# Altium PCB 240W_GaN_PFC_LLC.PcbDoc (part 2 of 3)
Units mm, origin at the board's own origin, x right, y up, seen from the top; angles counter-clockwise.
Board outline 105 x 71.8 mm, 4 copper layers (Top Layer, Layer 1, Layer 2, Bottom Layer), stack 1.787 mm thick; 165 components, 88 nets, 549 pads, 326 vias.
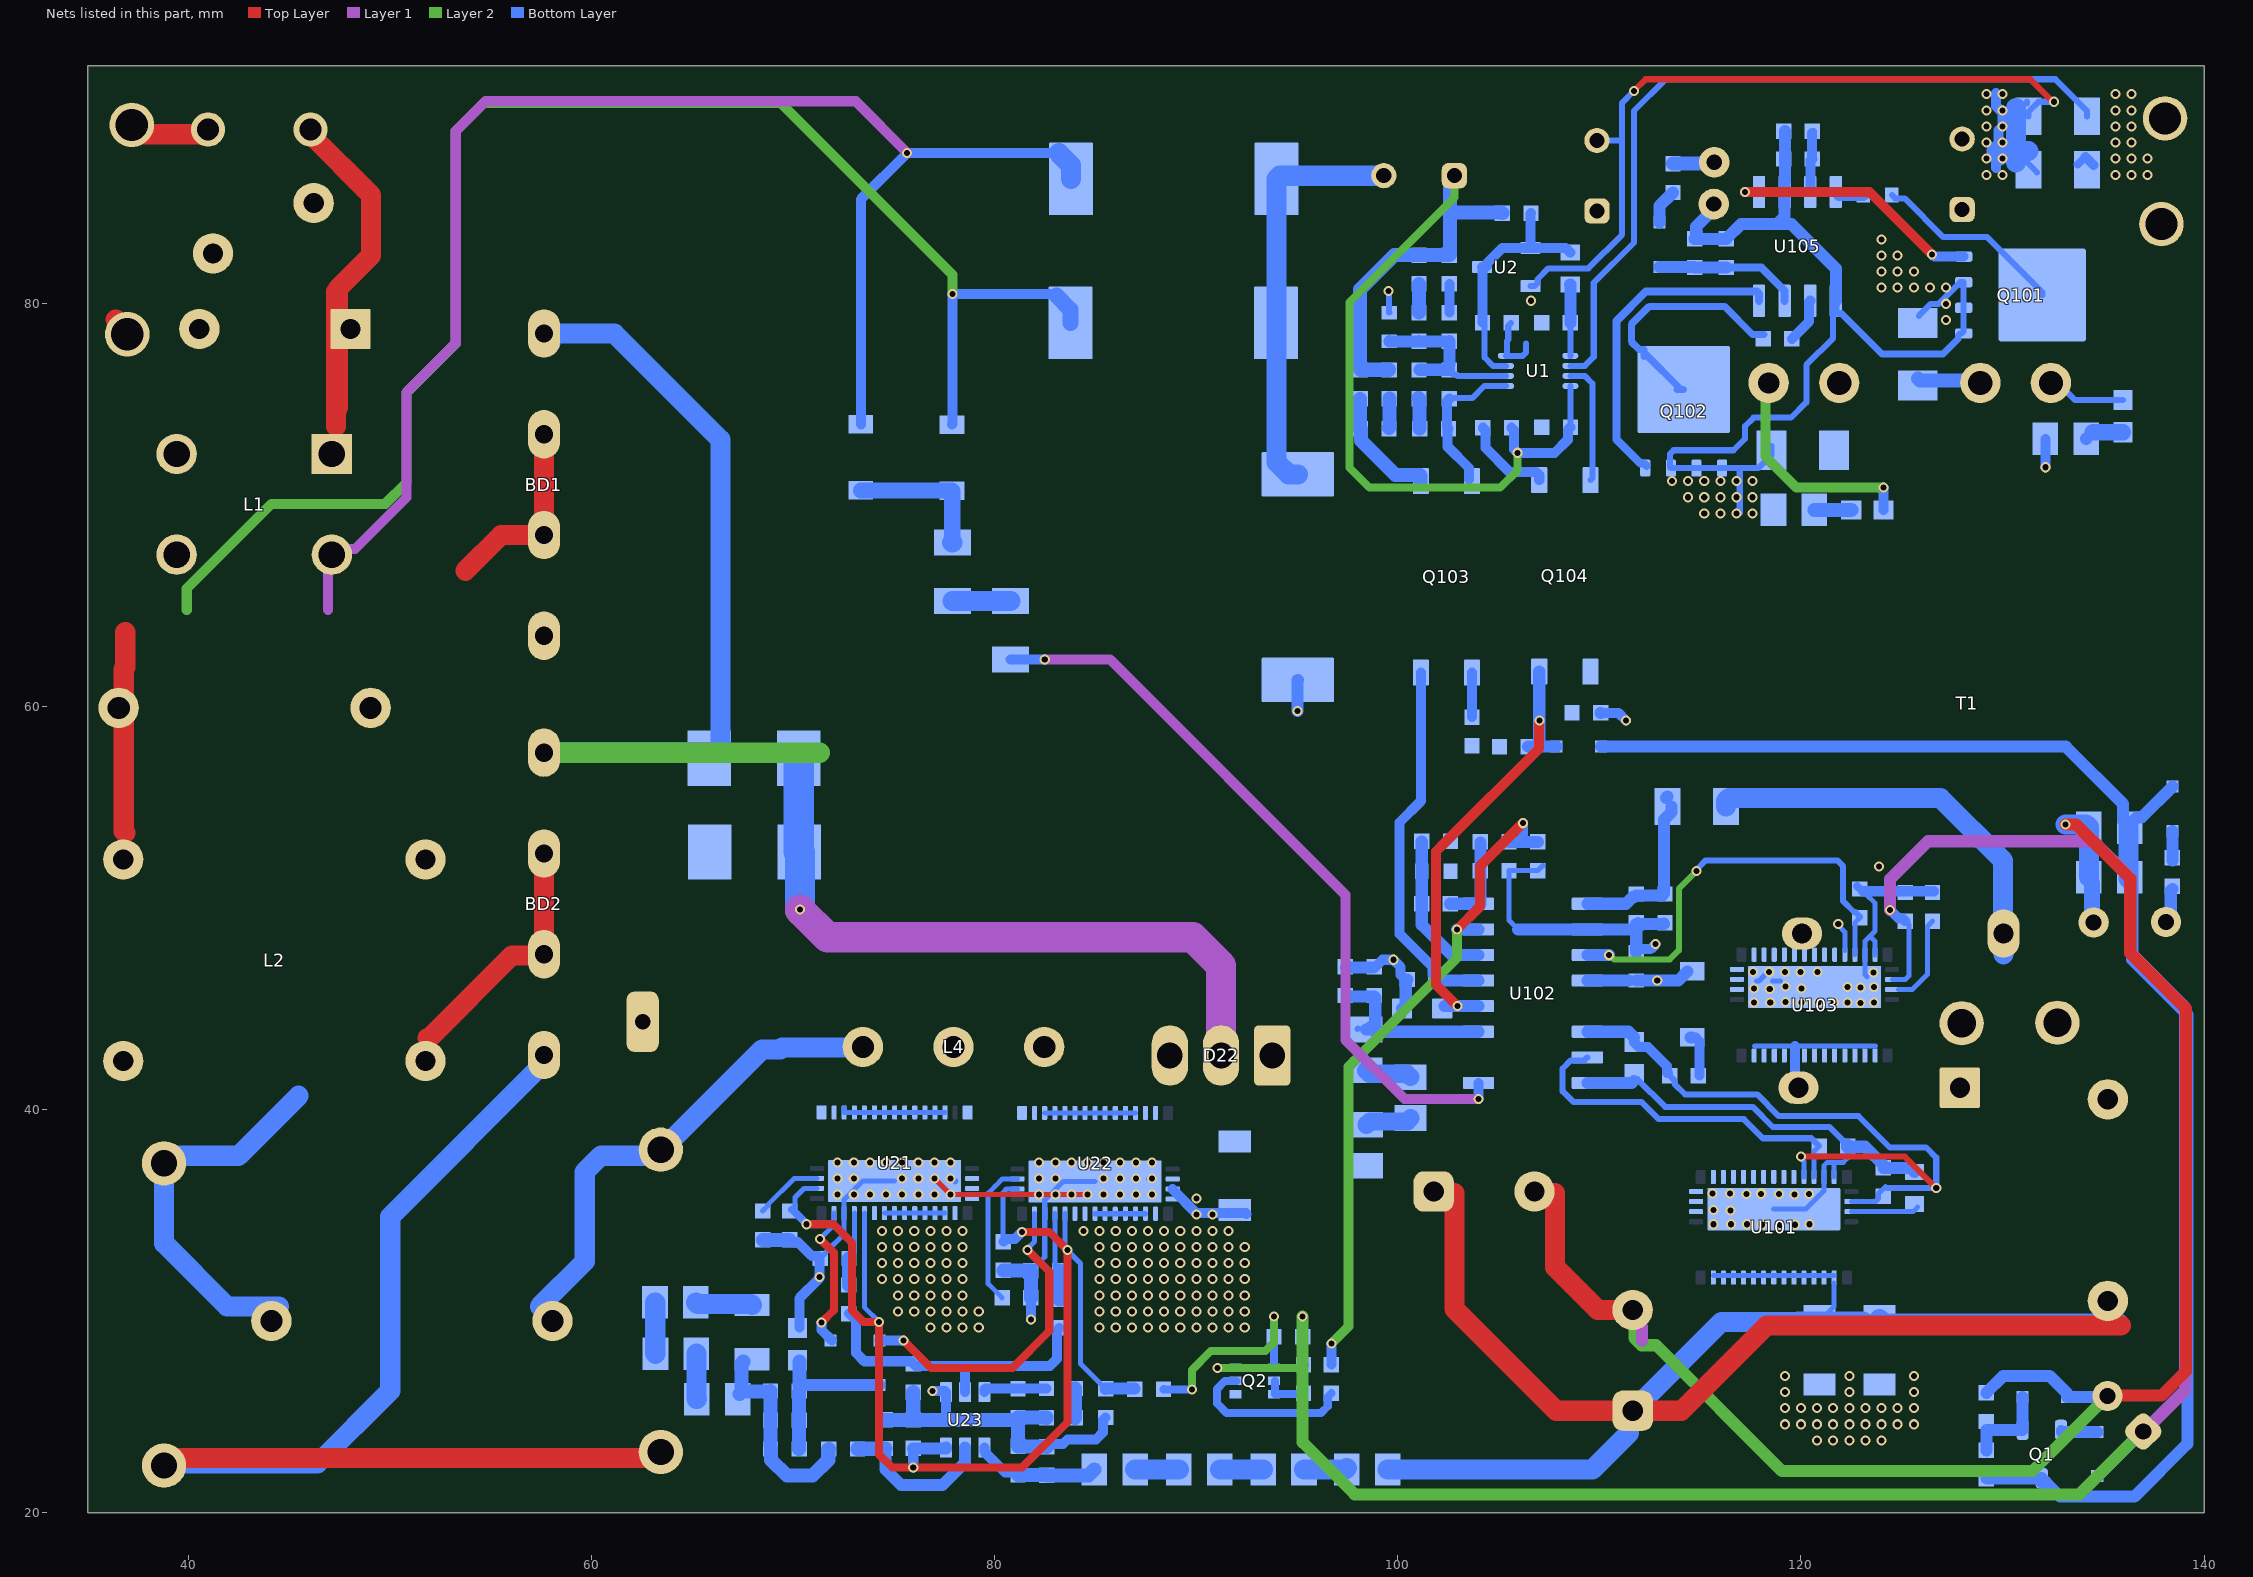
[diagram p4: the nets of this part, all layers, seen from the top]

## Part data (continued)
R109 R114 R115: library part CMP-0020707-3, "RES, 3.3 M, 5%, 0.125 W, AEC-Q200 Grade 0, 0805", Manufacturer=Panasonic, Power_W=125mW, Supplier Part Number 1=P3.3MACT-ND, TempCo="150 ppm/C", Tolerance_%=5%, Value2=0.125W, Value_Code=3M30, ValueDisplayed=3.3M
R110: library part CMP-0023050-5, "RES, 35.7 k, 1%, 0.1 W, 0603", Manufacturer=Yageo, Power_W=100mW, Supplier Part Number 1=311-35.7KHRCT-ND, TempCo="100 ppm/C", Tolerance_%=1%, Value2=0.1W, Value_Code=35k7, ValueDisplayed=35.7k
R111: library part CMP-0022804-5, "RES, 14.0 k, 1%, 0.1 W, 0603", Manufacturer=Yageo, Power_W=100mW, Supplier Part Number 1=311-14.0KHRCT-ND, TempCo="100 ppm/C", Tolerance_%=1%, Value2=0.1W, Value_Code=14k0, ValueDisplayed=14.0k
R112: library part CMP-0025886-5, "RES, 10 k, 5%, 0.1 W, 0603", Manufacturer=Yageo, Power_W=100mW, Supplier Part Number 1=311-10KGRCT-ND, TempCo="100 ppm/C", Tolerance_%=5%, Value2=0.1W, Value_Code=10k0, ValueDisplayed=10k
R113: library part CMP-0022201-4, "RES, 200, 1%, 0.1 W, 0603", Manufacturer=Vishay-Dale, Power_W=100mW, Supplier Part Number 1=541-200HCT-ND, TempCo="100 ppm/C", Tolerance_%=1%, Value2=0.1W, Value_Code=200R, ValueDisplayed=200
R116: library part CMP-0022588-5, "RES, 750, 1%, 0.1 W, AEC-Q200 Grade 0, 0603", Manufacturer=Vishay-Dale, Power_W=100mW, Supplier Part Number 1=541-750HCT-ND, TempCo="100 ppm/C", Tolerance_%=1%, Value2=0.1W, Value_Code=750R, ValueDisplayed=750
R117: library part CMP-0022735-5, "RES, 100 k, 1%, 0.1 W, 0603", Manufacturer=Yageo, Power_W=100mW, Supplier Part Number 1=311-100KHRCT-ND, TempCo="100 ppm/C", Tolerance_%=1%, Value2=0.1W, Value_Code=100k
R118: library part CMP-0080488-1, "RES, 10.0 k, 1%, 0.1 W, 0603", Manufacturer="TT Electronics/IRC", Power_W=100mW, TempCo="100 ppm/C", Tolerance_%=1%, Value2=0.1W, Value_Code=10k0, ValueDisplayed=10.0k
R119: library part CMP-0022706-2, "RES, 499 k, 1%, 0.1 W, AEC-Q200 Grade 0, 0603", Manufacturer=Panasonic, Power_W=100mW, Supplier Part Number 1=P499KHCT-ND, TempCo="100 ppm/C", Tolerance_%=1%, Value2=0.1W, Value_Code=499k
R120: library part CMP-0022618-3, "RES, 825 k, 1%, 0.1 W, AEC-Q200 Grade 0, 0603", Manufacturer=Vishay-Dale, Power_W=100mW, Supplier Part Number 1=541-825KHCT-ND, TempCo="100 ppm/C", Tolerance_%=1%, Value2=0.1W, Value_Code=825k
R121: library part CMP-0022768-4, "RES, 120 k, 1%, 0.1 W, 0603", Manufacturer=Yageo, Power_W=100mW, Supplier Part Number 1=311-120KHRCT-ND, TempCo="100 ppm/C", Tolerance_%=1%, Value2=0.1W, Value_Code=120k
R125: library part CMP-0022919-4, "RES, 221 k, 1%, 0.1 W, 0603", Manufacturer=Yageo, Power_W=100mW, Supplier Part Number 1=311-221KHRCT-ND, TempCo="100 ppm/C", Tolerance_%=1%, Value2=0.1W, Value_Code=221k
R126: library part CMP-0025768-4, "RES, 2.0 k, 5%, 0.1 W, AEC-Q200 Grade 0, 0603", Manufacturer=Vishay-Dale, Power_W=100mW, Supplier Part Number 1=541-2.0KGCT-ND, TempCo="200 ppm/C", Tolerance_%=5%, Value2=0.1W, Value_Code=2k00, ValueDisplayed=2.0k
R127: library part CMP-0022879-5, "RES, 1.47 k, 1%, 0.1 W, 0603", Manufacturer=Yageo, Power_W=100mW, Supplier Part Number 1=311-1.47KHRCT-ND, TempCo="100 ppm/C", Tolerance_%=1%, Value2=0.1W, Value_Code=1k47, ValueDisplayed=1.47k
R128 R129: library part CMP-0020631-3, "RES, 12, 5%, 0.125 W, AEC-Q200 Grade 0, 0805", Manufacturer=Panasonic, Power_W=125mW, Supplier Part Number 1=P12ACT-ND, TempCo="200 ppm/C", Tolerance_%=5%, Value2=0.125W, Value_Code=12R0, ValueDisplayed=12
R130 R131: library part CMP-0025912-5, "RES, 330, 5%, 0.1 W, 0603", Manufacturer=Yageo, Power_W=100mW, Supplier Part Number 1=311-330GRCT-ND, TempCo="100 ppm/C", Tolerance_%=5%, Value2=0.1W, Value_Code=330R, ValueDisplayed=330
R132: library part CMP-0022208-3, "RES, 210 k, 1%, 0.1 W, 0603", Manufacturer=Vishay-Dale, Power_W=100mW, Supplier Part Number 1=541-210KHCT-ND, TempCo="100 ppm/C", Tolerance_%=1%, Value2=0.1W, Value_Code=210k
RV1: library part CMP-0001908-4, "VARISTOR 450V 1.2KA DISC 7MM", Manufacturer=Littelfuse
T1: library part CMP-0123591-1, "LLC TRANSFORMER", Manufacturer=GCI, Operating Temperature Range=to
TP1 TP2 TP101 TP106: library part CMP-0055148-1, "Test Point, Multipurpose, Black, TH", Color=Black, Manufacturer=Keystone, PartNumber=5011, Supplier Part Number 1=36-5011-ND
U1: library part CMP-0040588-2, "36V, microPower, Rail-to-Rail Output, Dual, General Purpose Op Amp in microPackage, DCU0008A (VSSOP-8)", Manufacturer="Texas Instruments", Operating Temperature Range="-40 to 125 C", Rating=Catalog, Total Supply Voltage(Max)(+5V is 5, +/-5V is 10)=36, Total Supply Voltage(Min)(+5V is 5, +/-5V is 10)=2.7
U2: library part CMP-0033033-1, "Precision Micropower Shunt Voltage Reference, 1% accuracy, 2.5 V, 15 ppm / degC, 15 mA, -40 to 125 degC, 3-pin SOT-23 (DBZ), Green (RoHS & no Sb/Br)", Manufacturer="Texas Instruments", Rating=Catalog, Temp Coeff(Max)(ppm/ degree C)=150, Temp Coeff(Typ)(ppm/ degree C)=15
U21 U22 U101 U103: library part CMP-0096535-2, "650-V GaN FET With Integrated Driver and Current Sense Emulation", Manufacturer="Texas Instruments", Max Supply Voltage=26V, Min Supply Voltage=10V, Operating Temperature Range="-40°C to +175°C"
U23: library part CMP-0860501-1, "6-Pin Single-Phase Transition-Mode PFC Controller, DBV0006A (SOT-23-6)", Alternate Manufacturer="Texas Instruments", Operating Temperature Range="-40 to 125 C", Rating=Catalog
U102: library part CMP-0095300-2, "750kHz Wide VIN/VOUT Range LLC Controller Optimized for Light Load Efficiency", Manufacturer="Texas Instruments", Max Supply Voltage=18.5V, Operating Temperature Range="-40°C to +150°C", Switching Frequency=30-750kHz
U105: library part CMP-0121571-1, "Power Supply Controller Flyback, Forward Converters, LLC 8-SOIC", Digikey Part Number=1589-MP6924AGS-PTR-ND, Manufacturer="Monolithic Power Systems", Max Power Dissipation=1.4W, Max Supply Voltage=35V, Min Supply Voltage=4.2V, Mouser Part Number=946-MP6924AGS-P, Nominal Supply Current=4.6-16mA, Operating Temperature Range="-40°C to +125°C"

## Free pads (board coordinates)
  round 1.524 hole 0.762: 2(115.675,84.95) 2(115.7,87.025)
  round 2.2 hole 1.4: 2(132.725,44.325)
  rrect50% 1.6x3 hole 0.762 slot 2 at 90 deg: 13(62.525,44.375)

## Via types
v1: diameter 0.5, hole 0.3, Top Layer to Bottom Layer, tented both sides, 325 vias
v2: diameter 0.5, hole 0.2, Top Layer to Bottom Layer, tented both sides, 1 vias

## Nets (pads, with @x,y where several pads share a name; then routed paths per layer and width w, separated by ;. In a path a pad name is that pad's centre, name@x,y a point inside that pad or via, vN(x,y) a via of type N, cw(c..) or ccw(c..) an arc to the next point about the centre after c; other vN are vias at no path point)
5VP: C114.1 R119.2 R120.2 U102.8 | length 4.5
  Bottom Layer w0.6: R120.2@102.597,50.229 U102.8@104,50.229 104.089,50.229 C114.1@104.089,51.874 R119.2@104.089,53.272
390V_BUS: C29.1 C30.1 C31.1 C103.1 C122.1 C123.1 D21.1 D22.2 D25.1 R21.2 R109.1 U101.2 U101.3 U101.4 U101.5 U101.6 U101.7 U101.8 U101.9 U101.10 U101.11 U101.12 U101.13 U101.14 | length 125
  Top Layer w1: 102.8,35.875 102.8,30.124 107.849,25.075 C30.1@111.65,25.075 114.071,25.075 118.296,29.3 135.875,29.3
  Layer 1 w1.5: v1(70.325,49.935) 71.696,48.564 89.814,48.564 91.225,47.153 D22.2@91.225,42.7
  Bottom Layer w0.25: U101.14@115.65,31.775 U101.9@118.15,31.775 ; U101.8@118.65,31.775 U101.9@118.15,31.775 ; U101.5@120.15,31.775 U101.4@120.65,31.775 ; C122.1@120.925,29.625 121.025,29.625 121.65,30.25 U101.2@121.65,31.4 ; U101.2@121.65,31.775 U101.4@120.65,31.775 ; U101.9@118.15,31.775 U101.4@120.65,31.775
  Bottom Layer w1: R21.2@99.491,22.15 109.649,22.15 111.459,23.96 111.459,24.884 C30.1@111.65,25.075 116.05,29.475 119.85,29.475 119.862,29.488 122.837,29.488 122.85,29.5 123.075,29.5 ; C123.1@123.9,29.625 124.125,29.4 135.775,29.4
  Bottom Layer w1.5: D25.1@70.26,57.45 70.273,57.437 70.273,52.812 D21.1@70.285,52.8 70.325,52.76 v1(70.325,49.935)
BD+: BD1.1 BD2.1 C25.1 D21.2 D25.2 L22.1 | length 68.9
  Layer 2 w1: BD2.1@57.625,57.725 71.315,57.725
  Bottom Layer w1: L22.1@44.475,30.25 41.9,30.25 38.775,33.375 38.775,37.725 42.475,37.725 45.45,40.7 ; BD2.1@57.625,57.725 66.382,57.725 66.382,73.268 61.123,78.527 57.948,78.527 57.948,78.05 57.625,78.373 BD1.1@57.625,78.527
FB: C116.1 Q103.6 U102.5 | length 18.5
  Bottom Layer w0.4: C116.1@101.95,46.467 C116.1@101.975,46.467
  Bottom Layer w0.5: Q103.6@101.138,61.7 101.138,55.318 100.079,54.26 100.079,48.739 101.725,47.093 101.725,46.692 C116.1@101.95,46.467
  Bottom Layer w0.6: C116.1@101.975,46.419 U102.5@104,46.419
HB: C101.1 C121.2 R106.2 U101.30 U101.36 U102.14 | length 34.7
  Top Layer w0.3: v1(120,37.681) 125.157,37.681 126.697,36.141 v1@126.719,36.141
  Bottom Layer w0.25: U101.36@122.5,35.45 123.704,35.45 123.85,35.596 123.85,35.85 124.2,36.2
  Bottom Layer w0.254: v1(120,37.681) 120,37.585 120.15,37.435 U101.30@120.15,36.675
  Bottom Layer w0.3: R106.2@113.489,41.7 113.72,41.469 113.72,41.299 114.245,40.774 117.824,40.774 118.905,39.693 122.854,39.693 124.413,38.133 126.214,38.133 126.713,37.634 126.713,36.15 v1@126.726,36.137 ; 124.301,36.125 v1(126.713,36.125)
  Bottom Layer w0.5: C121.2@111.725,43.591 111.725,43.35 111.95,43.125 112.397,43.125 113.358,42.165 113.358,41.831 R106.2@113.408,41.831
  Bottom Layer w0.6: U102.14@109.4,43.879 111.437,43.879 C121.2@111.725,43.591
HO: C102.1 U101.31 U102.15 | length 18.1
  Bottom Layer w0.25: U101.31@120.65,36.675 120.65,37.947 C102.1@120.903,38.2
  Bottom Layer w0.3: U102.15@109.4,42.609 109.25,42.459 108.58,42.459 108.175,42.054 108.175,40.926 108.707,40.394 110.375,40.394 112.085,40.394 112.94,39.539 117.166,39.539 118.112,38.593 120.51,38.593 C102.1@120.903,38.2
HV: R2.1 U102.1 | length 37.3
  Layer 1 w0.5: v1(82.475,62.348) 85.722,62.348 97.392,50.678 97.392,43.48 100.334,40.537 v1(104,40.537)
  Bottom Layer w0.5: R2.1@80.775,62.35 80.777,62.348 v1(82.475,62.348) ; v1(104,40.537) U102.1@104,41.339
ISNS: C108.2 C120.1 R113.2 U102.9 | length 8.5
  Bottom Layer w0.6: U102.9@109.4,50.229 111.314,50.229 111.652,50.566 111.744,50.566 111.825,50.647 R113.2@113.119,50.647 ; R113.2@113.2,50.75 113.2,54.401 113.575,54.776 C108.2@113.575,55.051 ; C108.2@113.3,55.476 C108.2@113.375,55.551
LL: C5.1 R120.1 R132.2 U102.6 | length 7.6
  Bottom Layer w0.6: C5.1@101.189,53.325 101.182,53.318 101.182,50.229 101.182,49.186 102.688,47.68 103.371,47.68 103.379,47.689 U102.6@104,47.689
LMG_VCC: C21.2 C23.2 C36.1 C39.1 R32.1 U21.30 U21.36 U22.30 U22.36 U23.3 | length 65.8
  Top Layer w0.4: v1(70.65,34.325) 71.994,34.325 72.911,33.408 72.911,30.053 73.489,29.475 v1(74.255,29.475) 74.255,22.905 74.91,22.25 v1(75.95,22.25) 81.35,22.25 ; 77.868,22.25 81.35,22.25 ; v1(81.35,33.95) 82.7,33.95 v1(83.6,33.05) 83.6,24.5 81.35,22.25
  Bottom Layer w0.25: C21.2@69.975,35.136 70.081,35.242 70.081,35.656 70.525,36.1 U21.36@71.175,36.1 ; U21.30@73.525,34.875 73.525,30.211 v1@74.265,29.471 ; C23.2@80.425,33.461 80.397,33.489 80.397,35.891 80.579,36.073 U22.36@81.125,36.073 ; v1@83.475,33.155 U22.30@83.475,34.848 ; v1@83.6,33.028 84.255,32.373 84.255,27.401 C36.1@85.495,26.161
  Bottom Layer w0.254: v1@81.283,33.95 v1(81.35,33.95)
  Bottom Layer w0.4: C21.2@69.946,35.056 70.65,34.352 v1(70.65,34.325)
  Bottom Layer w0.5: v1(75.95,22.25) C39.1@75.95,23.2 ; C23.2@80.425,33.461 80.556,33.592 80.992,33.592 v1(81.35,33.95)
  Bottom Layer w0.6: C39.1@75.95,23.2 C39.1@75.948,23.202 77.577,23.202 U23.3@77.577,23.243 ; C36.1@85.495,26.161 85.502,26.168 86.928,26.168 R32.1@86.935,26.175
LO: C111.1 U102.11 U103.31 | length 21.4
  Layer 2 w0.3: v1(110.475,47.675) 110.529,47.675 110.73,47.474 113.499,47.474 113.943,47.918 113.943,50.983 114.8,51.84 v1@114.8,51.875
  Bottom Layer w0.25: U103.31@122.675,47.7 122.675,49.283 122.942,49.55 C111.1@122.95,49.55
  Bottom Layer w0.3: v1@114.85,51.955 115.274,52.379 121.801,52.379 ; 121.84,52.34 122.095,52.085 122.095,50.357 122.632,49.82 122.694,49.82 C111.1@122.925,49.589
  Bottom Layer w0.6: U102.11@109.4,47.689 v1@110.461,47.689
  other v1: 114.816,51.856
NetBD1_2: BD1.2 BD1.3 L2.3 | length 9.6
  Top Layer w1: 53.725,66.75 55.502,68.527 BD1.3@57.625,68.527 BD1.2@57.625,73.527
NetBD2_2: BD2.2 BD2.3 L2.4 | length 12.5
  Top Layer w1: 51.85,43.575 51.952,43.575 56.037,47.66 57.56,47.66 BD2.3@57.625,47.725 BD2.2@57.625,52.725
NetC1_1: C1.1 F1.1 L1.1 RV1.1 | length 28
  Top Layer w1: F1.1@46.015,88.425 49.05,85.39 49.05,82.95 49.05,82.4 47.4,80.75 47.4,74.837 ; 47.3,73.925 47.3,74.837 ; 47.3,74.837 47.3,80.6 47.3,74.837
NetC1_2: C1.2 L1.4 RV1.2 TP1.1 | length 1.1
  Top Layer w1: TP1.1@36.375,79.226 36.95,78.651 TP1.1@36.95,78.324
NetC2_1: C2.1 CY1.1 D3.2 L1.3 L2.2 | length 87.6
  Top Layer w1: C2.1@36.775,59.95 36.775,61.875 ; 36.85,53.75 36.775,53.825 36.775,61.875 ; 36.852,63.702 36.852,61.952 36.775,61.875
  Layer 2 w0.5: 39.9,64.8 39.9,65.869 44.106,70.075 49.75,70.075 50.8,71.125 50.8,75.589 53.25,78.039 53.25,88.575 54.65,89.975 69.368,89.975 77.903,81.44 77.903,80.488 v1(77.9,80.484)
  Bottom Layer w0.5: D3.2@77.875,74 77.9,74.025 v1(77.9,80.484) 82.979,80.484 CY1.1@83.05,80.413
  Bottom Layer w0.8: CY1.1@83.05,80.413 83.75,79.713 CY1.1@83.75,79.05
NetC2_2: C2.2 CY2.1 D2.2 L1.2 L2.1 | length 74.9
  Layer 1 w0.5: 46.9,64.8 46.9,67.9 47.001,67.799 47.04,67.837 48.25,67.837 50.8,70.387 50.8,75.608 53.25,78.058 53.25,88.575 54.725,90.05 73.096,90.05 v1@75.671,87.475
  Bottom Layer w0.5: D2.2@73.35,74.013 73.35,85.182 v1(75.643,87.475) CY2.1@83.175,87.475
  Bottom Layer w1: CY2.1@83.175,87.475 83.775,86.875 CY2.1@83.775,86.2
NetC7_1: C7.1 R110.2 R115.1 U102.3 | length 8.4
  Bottom Layer w0.3: R115.1@98,44.025 R115.1@98.025,44.05 ; C7.1@98.819,45.619 C7.1@98.825,45.614 ; C7.1@98.819,45.691 C7.1@98.825,45.685
  Bottom Layer w0.6: R110.2@97.465,45.619 C7.1@98.819,45.619 ; R115.1@98.425,43.991 98.54,43.991 98.875,44.326 98.875,45.564 C7.1@98.825,45.614 ; R115.1@98.873,43.879 U102.3@104,43.879
NetC8_2: C8.2 R10.2 | length 1.4
  Bottom Layer w0.5: R10.2@102.55,79.561 C8.2@102.55,80.989
NetC9_1: C9.1 D4.1 Q1.1 R4.1 | length 4.4
  Bottom Layer w0.6: R4.1@129.2,23.111 129.2,24.125 Q1.1@131,24.125 131,25.525 D4.1@131,25.75
NetC10_1: C10.1 R9.1 R125.2 U1.3 U2.1 U2.3 | length 12.4
  Bottom Layer w0.254: C10.1@104.187,79.062 C10.1@104.2,79.05 C10.1@104.3,78.95 ; U1.3@105.35,76.929 U1.3@105.359,76.92
  Bottom Layer w0.3: C10.1@104.3,78.95 104.3,77.334 104.715,76.918 105.107,76.918 105.109,76.92 U1.3@105.357,76.92
  Bottom Layer w0.5: U2.3@104.175,81.825 104.375,81.825 104.425,81.875 104.425,82.008 105.192,82.775 U2.1@106.575,82.775 ; C10.1@104.187,79.062 U2.3@104.187,81.813 ; R9.1@106.602,84.499 106.589,84.486 106.589,82.789 U2.1@106.575,82.775 ; R125.2@108.55,82.55 108.325,82.775 U2.1@106.575,82.775
NetC22_1: C22.1 R34.2 U21.31 | length 3.3
  Bottom Layer w0.25: C22.1@73.025,32.89 U21.31@73.025,34.875
  Bottom Layer w0.7: R34.2@72.77,31.317 C22.1@72.77,32.635
NetC24_1: C24.1 R38.1 U22.31 | length 4.3
  Bottom Layer w0.25: U22.31@82.975,34.848 82.975,32.261 C24.1@83.211,32.025
  Bottom Layer w0.7: R38.1@83.211,30.606 C24.1@83.211,32.025
NetC27_1: C27.1 L4.2 L22.2 | length 23.5
  Bottom Layer w1: L22.2@57.425,30.25 59.65,32.475 59.65,36.925 60.45,37.725 63.175,37.725 68.454,43.004 69.354,43.004 69.45,43.1 L4.2@72.95,43.1
NetC28_1: C28.1 D22.1 D22.3 L4.4 R22.2 U21.1 U21.2 U21.3 U21.4 U21.5 U21.6 U21.7 U21.8 U21.9 U21.10 U21.11 U21.12 U21.13 U21.15 U22.1 U22.2 U22.3 U22.4 U22.5 U22.6 U22.7 U22.8 U22.9 U22.10 U22.11 U22.12 U22.13 U22.14 | length 13.4
  Bottom Layer w0.254: U21.3@72.525,40.096 U21.3@72.525,39.875 U21.4@73.025,39.875 U21.5@73.525,39.875 U21.6@74.025,39.875 U21.7@74.525,39.875 U21.8@75.025,39.875 U21.9@75.525,39.875 U21.10@76.025,39.875 U21.11@76.525,39.875 U21.12@77.025,39.875 U21.13@77.525,39.875 ; U22.3@82.475,39.848 U22.4@82.975,39.848 U22.5@83.475,39.848 U22.6@83.975,39.848 U22.7@84.475,39.848 U22.8@84.975,39.848 U22.9@85.475,39.848 U22.10@85.975,39.848 U22.11@86.475,39.848 U22.12@86.975,39.848
  Bottom Layer w1: R22.2@65.166,30.45 65.241,30.375 67.9,30.375 C28.1@67.95,30.325 ; D22.3@88.685,41.884 D22.3@88.685,42.7
NetC28_2: C28.2 C32.1 C33.1 R27.1 R29.2 R33.2 | length 10.4
  Bottom Layer w0.7: R27.1@67.325,25.9 R27.1@67.433,26.008 ; C28.2@67.525,27.5 67.508,27.5 67.433,27.425 R27.1@67.433,26.008 ; C32.1@68.864,23.375 R29.2@68.864,24.6 C33.1@68.864,26.05 68.833,26.019 67.444,26.019 R27.1@67.433,26.008 ; C32.1@68.895,23.206 68.895,22.635 69.68,21.85 70.948,21.85 71.733,22.635 71.733,23.144 R33.2@71.764,23.175
NetC37_1: C37.1 C38.1 U23.6 | length 3.2
  Bottom Layer w0.5: U23.6@79.477,25.993 79.477,26.125 79.527,26.175 C37.1@82.564,26.175
NetC37_2: C37.2 R35.2 | length 1.4
  Bottom Layer w0.7: R35.2@83.986,24.725 C37.2@83.986,26.175
NetC40_1: C40.1 R33.1 U23.2 | length 7.9
  Bottom Layer w0.6: C40.1@74.564,23.195 74.564,22.164 75.336,21.393 77.409,21.393 78.527,22.51 U23.2@78.527,23.243
  Bottom Layer w0.7: R33.1@73.186,23.175 73.196,23.185 74.554,23.185 C40.1@74.564,23.195
NetC41_1: C41.1 R30.1 R37.2 U23.1 | length 6.3
  Bottom Layer w0.5: U23.1@79.477,23.243 79.477,23.043 80.504,22.017 C41.1@81.022,22.017 ; C41.1@81.019,22.02 C41.1@81.022,22.017 ; C41.1@81.094,22.017 C41.1@81.022,22.017 ; C41.1@81.15,21.889 C41.1@81.022,22.017
  Bottom Layer w0.7: C41.1@81.15,21.889 81.162,21.876 82.562,21.876 R37.2@82.575,21.864 84.649,21.864 R30.1@84.934,22.15
NetC103_2: C103.2 C108.1 C109.1 pad.2@132.725,44.325 | length 20.1
  Bottom Layer w1: C108.1@116.275,55.051 116.275,55.325 116.425,55.475 126.917,55.475 130.032,52.359 C109.1@130.032,49.232 ; C109.1@130.05,47.725 130.05,48.775 C109.1@130.05,49.3
NetC113_2: C113.2 R116.2 | length 1.5
  Bottom Layer w0.7: R116.2@99.567,73.831 99.567,73.893 99.574,73.9 C113.2@99.575,75.289
NetC118_1: C118.1 R10.1 R103.1 R104.2 R118.2 U1.2 | length 8.6
  Bottom Layer w0.3: C118.1@102.55,76.711 102.781,76.48 102.897,76.48 102.957,76.42 U1.2@105.359,76.42
  Bottom Layer w0.6: R104.2@99.575,78.139 99.595,78.119 R103.1@101.05,78.119 ; R103.1@101.05,78.139 R103.1@101.05,78.119 ; R118.2@101.068,76.729 C118.1@102.532,76.729 ; C118.1@102.55,76.99 R10.1@102.55,78.139 102.53,78.119 R103.1@101.05,78.119
NetC118_2: C118.2 C119.2 Q103.3 U1.1 | length 7.6
  Bottom Layer w0.3: C118.2@102.55,75.315 103.683,75.315 104.288,75.92 U1.1@105.359,75.92
  Bottom Layer w0.5: C118.2@102.55,75.289 102.439,75.178 102.439,73.872 C119.2@102.511,73.8 102.471,73.76 102.471,72.904 103.528,71.847 Q103.3@103.528,71.275
NetC119_1: C119.1 R118.1 | length 1.5
  Bottom Layer w0.7: R118.1@101.019,75.32 101.063,75.275 C119.1@101.063,73.825
NetC125_1: C125.1 R128.1 | length 2
  Bottom Layer w0.6: R128.1@134.156,73.301 R128.1@134.48,73.625
  Bottom Layer w0.8: R128.1@134.48,73.625 C125.1@135.975,73.625
NetC126_1: C126.1 R129.1 | length 1.8
  Bottom Layer w0.7: R129.1@120.667,69.775 C126.1@122.497,69.775
NetC127_2: C127.2 R107.2 U105.3 | length 3.2
  Bottom Layer w0.3: U105.3@120.46,85.55 U105.3@120.547,85.638 ; R107.2@120.547,88.475 R107.2@120.635,88.562
  Bottom Layer w0.5: U105.3@120.482,85.572 120.482,87.11 C127.2@120.56,87.187 ; C127.2@120.547,87.187 R107.2@120.547,88.475
NetD1_2: D1.2 Q1.2 | length 1.9
  Bottom Layer w0.5: Q1.2@132.9,24.125 132.9,24.075 Q1.2@132.95,24.025
  Bottom Layer w0.6: Q1.2@132.95,24.025 D1.2@134.7,24.025
NetD2_1: D2.1 D3.1 R1.2 | length 7.1
  Bottom Layer w0.8: D2.1@73.362,70.737 77.863,70.737 D3.1@77.875,70.725 ; R1.2@77.888,68.162 D3.1@77.888,70.712
  Bottom Layer w1: R1.2@77.888,68.162 R1.2@77.9,68.15
NetD5_2: D5.2 R8.2 | length 1.8
  Bottom Layer w0.6: D5.2@112.975,84.025 112.975,84.85 R8.2@113.65,85.525
NetD23_2: D23.2 U21.33 | length 7.4
  Top Layer w0.4: v1(71.325,33.6) 72.009,32.916 72.009,30.059 v1(71.4,29.45)
  Bottom Layer w0.25: v1@71.325,33.606 72.025,34.306 U21.33@72.025,34.875
  Bottom Layer w0.5: v1(71.4,29.45) 71.4,29.075 D23.2@71.925,28.55
NetD24_2: D24.2 U22.33 | length 16.2
  Top Layer w0.4: v1(75.473,28.553) 76.826,27.2 80.875,27.2 82.7,29.025 82.7,31.975 v1(81.625,33.05)
  Bottom Layer w0.25: v1(81.625,33.05) 81.625,33.118 81.975,33.468 U22.33@81.975,34.848
  Bottom Layer w0.5: D24.2@74.275,28.55 75.471,28.55 v1(75.473,28.553)
NetD101_2: D101.2 R123.1 | length 1.5
  Bottom Layer w0.6: R123.1@138.431,52.379 D101.2@138.431,53.84
NetD102_1: D102.1 R106.1 | length 2.2
  Bottom Layer w0.5: D102.1@114.6,43.6 114.753,43.6 114.961,43.391 R106.1@114.961,41.7
  Bottom Layer w0.6: D102.1@114.525,43.6 D102.1@114.6,43.6
NetF1_2: F1.2 TP2.1 | length 3.8
  Top Layer w1: TP2.1@37.125,88.4 37.137,88.413 40.922,88.413 F1.2@40.935,88.425
NetL3_1: L3.1 T1.1
NetQ2_2: Q2.2 R7.2 | length 8.4
  Bottom Layer w0.4: Q2.2@92,26.55 91.99,26.54 91.41,26.54 91.019,26.148 91.019,25.44 91.495,24.964 96.191,24.964 96.519,25.291 96.519,25.758 R7.2@96.7,25.939
NetQ2_4: Q2.4 R5.2 R32.2 | length 10.9
  Layer 2 w0.4: v1(89.775,26.125) 89.775,27.096 90.713,28.034 93.421,28.034 93.85,28.463 v1(93.85,29.75)
  Bottom Layer w0.4: R32.2@88.369,26.137 88.375,26.131 v1@89.769,26.131 ; Q2.4@93.85,27.2 Q2.4@93.85,27.2 93.851,28.749 R5.2@93.853,28.75 93.851,28.751 93.851,29.749 v1(93.85,29.75)
NetQ2_5: Q2.5 Q2.6 R6.1 | length 2.1
  Bottom Layer w0.4: Q2.5@93.9,26.55 93.9,25.9 93.91,25.91 95.18,25.91 95.26,25.99 R6.1@95.317,25.933
NetQ103_1: Q103.1 R116.1 R117.1 | length 6
  Bottom Layer w0.7: R116.1@98.119,73.805 R117.1@98.119,75.283 ; R116.1@98.145,73.8 98.17,73.775 98.17,73.217 99.887,71.5 101.088,71.5 101.125,71.462 Q103.1@101.125,71.2
NetQ103_4: Q103.4 R112.2 | length 2.2
  Bottom Layer w0.5: R112.2@103.678,59.486 Q103.4@103.678,61.7
NetQ104_1: Q104.1 R126.2 | length 4.5
  Bottom Layer w0.5: R126.2@104.214,73.85 104.345,73.719 104.345,73.427 ; 104.346,73.426 104.346,72.854 105.554,71.646 106.863,71.646 107.013,71.496 Q104.1@107.013,71.25
NetQ104_3: Q104.3 U1.7 | length 6.1
  Bottom Layer w0.3: U1.7@108.559,76.42 109.273,76.42 109.657,76.036 109.657,71.355 Q104.3@109.553,71.25
NetR1_1: R1.1 R2.2 | length 2.9
  Bottom Layer w1: R1.1@77.9,65.25 R2.2@80.775,65.25
NetR3_1: R3.1 R103.2 | length 1.4
  Bottom Layer w0.7: R103.2@101.05,79.561 R3.1@101.05,80.989
NetR21_1: R21.1 R23.2 | length 2.2
  Bottom Layer w0.254: R23.2@95.338,22.222 R23.2@95.341,22.222
  Bottom Layer w1: R23.2@95.341,22.15 97.392,22.15 R21.1@97.464,22.222
NetR22_1: R22.1 R26.2 | length 2.6
  Bottom Layer w1: R22.1@63.134,30.45 63.146,30.437 63.146,27.913 R26.2@63.159,27.9
NetR23_1: R23.1 R28.2 | length 2.1
  Bottom Layer w1: R28.2@91.166,22.15 R23.1@93.309,22.15
NetR24_2: R24.2 U21.37 | length 3.4
  Bottom Layer w0.25: R24.2@68.475,34.986 68.731,35.242 68.731,35.287 70.044,36.6 U21.37@71.175,36.6
NetR25_2: R25.2 U22.37 | length 7.2
  Bottom Layer w0.25: R25.2@80.364,30.675 79.669,31.37 79.669,35.87 80.015,36.216 80.372,36.573 U22.37@81.125,36.573
NetR26_1: R26.1 R27.2 | length 2.3
  Bottom Layer w1: R26.1@65.191,27.9 65.2,27.891 65.2,25.656 R27.2@65.209,25.647
NetR28_1: R28.1 R30.2 | length 2.2
  Bottom Layer w1: R30.2@86.966,22.15 R28.1@89.134,22.15
NetR101_2: R101.2 U101.37 | length 3.4
  Bottom Layer w0.25: U101.37@122.5,34.95 125.57,34.95 R101.2@125.793,35.173
NetR105_2: R105.2 U103.37 | length 4.5
  Bottom Layer w0.25: U103.37@124.85,45.975 125.525,45.975 126.281,46.731 126.281,49.12 R105.2@126.525,49.364
NetR109_2: R109.2 R114.2 | length 2.3
  Bottom Layer w0.9: R109.2@98.45,39.266 98.615,39.431 100.46,39.431 R114.2@100.625,39.595
NetR114_1: R114.1 R115.2 | length 2.3
  Bottom Layer w0.9: R115.2@98.425,41.959 98.591,41.793 100.459,41.793 R114.1@100.625,41.627
NetR123_2: R123.2 T1.3 | length 1.8
  Bottom Layer w0.6: T1.3@138.109,49.325 138.109,49.569 138.35,49.809 138.35,50.875 R123.2@138.431,50.956
NetR125_1: R125.1 R127.2 U1.5 | length 3.4
  Bottom Layer w0.3: U1.5@108.559,77.42 R127.2@108.559,78.888
  Bottom Layer w0.6: R125.1@108.55,80.95 108.555,80.945 108.555,79.06 R127.2@108.559,79.056
NetR130_2: R130.2 U105.4 | length 1.4
  Bottom Layer w0.3: U105.4@121.73,85.55 U105.4@121.88,85.4
  Bottom Layer w0.6: U105.4@121.88,85.4 R130.2@123.089,85.4
NetR131_2: R131.2 U105.6 | length 2.3
  Bottom Layer w0.5: R131.2@119.55,78.261 120.405,79.116 120.405,80.095 U105.6@120.46,80.15
OCP: R102.2 R122.2 TP106.1 U1.6 | length 39.5
  Bottom Layer w0.3: U1.6@108.559,76.92 109.273,76.92 109.718,77.364 109.718,81.033 111.715,83.031 111.715,89.576 113.281,91.142 132.621,91.142 134.189,89.574 R122.2@134.189,89.299
  Bottom Layer w0.4: R102.2@133.736,86.906 R102.2@134.118,87.289
  Bottom Layer w0.5: R102.2@134.118,87.289 R102.2@134.518,86.889
  other v1: 135.6,86.4 136.4,86.4 137.2,86.4 135.6,87.2 136.4,87.2 137.2,87.2 135.6,88 136.4,88 135.6,88.8 136.4,88.8 135.6,89.6 136.4,89.6 135.6,90.4 136.4,90.4
OTP: D103.2 Q104.6 R108.2 R111.2 U102.4 | length 23.2
  Top Layer w0.3: 102.349,53.276 102.35,53.275
  Top Layer w0.5: v1@102.944,45.15 101.89,46.205 101.89,52.817 102.349,53.276 107.011,57.938 v1@107.011,59.247
  Bottom Layer w0.6: R108.2@102.324,45.149 U102.4@104,45.149 ; R111.2@106.461,58.025 D103.2@107.875,58.025 ; 107.013,58.194 v1@107.013,59.247 ; v1@107.013,59.325 Q104.6@107.013,61.75
  other v1: 102.95,45.15 107.025,59.325
PFC_CS: C32.2 C33.2 D23.1 D24.1 R29.1 R31.2 | length 7.7
  Bottom Layer w0.6: C33.2@70.59,26.354 71.846,26.354 D23.1@71.85,26.35 D24.1@74.275,26.35
  Bottom Layer w0.7: C32.2@70.286,23.175 R29.1@70.286,24.6 C33.2@70.286,26 ; C33.2@70.3,26.333 R31.2@70.3,27.5
PFC_G: R34.1 R36.2 R38.2 U23.5 | length 15.4
  Bottom Layer w0.5: R34.1@72.77,29.895 73.117,29.548 73.117,27.933 73.522,27.528 75.833,27.528 76.067,27.294 78.527,27.294 ; U23.5@78.527,25.993 78.527,27.294 ; R38.2@83.211,29.183 83.08,29.052 83.08,27.649 82.725,27.294 78.527,27.294
PGND: BD1.4 BD2.4 C4.2 C5.2 C7.2 C9.2 C21.1 C22.2 C23.1 C24.2 C25.2 C27.2 C29.2 C30.2 C31.2 C36.2 C38.2 C39.2 C40.2 C41.2 C109.2 C110.2 C111.2 C112.2 C112A.2 C114.2 C116.2 C117.1 C120.2 C122.2 C123.2 C128.1 CY101.2 D4.2 L4.3 pad.13 Q2.1 Q104.4 R24.1 R25.1 R31.1 R35.1 R36.1 R37.1 R105.1 R108.1 R110.1 R111.1 R112.1 R113.1 R121.1 R132.1 T1.4 U21.17 U21.18 U21.19 U21.21 U21.22 U21.23 U21.24 U21.25 U21.26 U21.27 U21.28 U21.29 U21.32 U21.39 U22.17 U22.18 U22.19 U22.21 U22.22 U22.23 U22.24 U22.25 U22.26 U22.27 U22.28 U22.29 U22.32 U22.39 U23.4 U102.10 U103.17 U103.18 U103.19 U103.21 U103.22 U103.23 U103.24 U103.25 U103.26 U103.27 U103.28 U103.29 U103.32 U103.33 U103.39 | length 235.6
  Top Layer w0.254: v1(77,36.6) v1(77.8,35.8) v1(82.2,35.8) v1(83,35.8) v1(83.8,35.8) v1(84.6,35.8)
  Top Layer w0.6: v1(133.125,54.165) 133.648,54.165 136.339,51.473 136.339,47.786 139.1,45.025 139.1,27.025 137.9,25.825 C4.2@135.232,25.825
  Top Layer w1: C25.2@38.775,22.725 C27.2@63.175,22.725 ; 107.8,35.875 107.8,32.194 109.919,30.075 C30.2@111.65,30.075
  Layer 1 w0.6: C30.2@111.65,30.075 111.65,29.696 112.108,29.238 112.108,28.552
  Layer 2 w0.6: C30.2@111.616,29.967 111.736,29.847 111.736,28.674 112.087,28.322 112.814,28.322 119.062,22.075 131.482,22.075 C4.2@135.216,25.809
  Bottom Layer w0.25: v1@71.3,31.55 v1@71.3,31.65 ; 72.523,33.846 72.525,33.848 U21.32@72.525,34.875 72.525,35.55 73.45,36.475 U21.39@75.025,36.475 ; C24.2@81.803,32.039 82.475,32.711 U22.32@82.475,34.848 82.475,35.523 83.4,36.448 U22.39@84.975,36.448 ; 105.969,48.95 105.511,49.408 C114.2@105.511,51.874 ; R121.1@107.196,52.131 R121.1@106.94,51.875 C114.2@105.511,51.874 ; U103.39@117.8,46.4 117.915,46.4 U103.39@118.465,46.95 ; U103.39@118.6,46.4 U103.39@118.995,46.4 ; C111.2@123.087,50.85 123.087,50.799 123.181,50.705 123.232,50.705 123.681,50.256 123.681,48.874 123.428,48.621 123.175,48.368 ; 123.175,48.325 U103.32@123.175,47.7 123.175,46.7 U103.39@123.275,46.6 ; C114.2@105.511,51.874 C114.2@105.511,51.874
  Bottom Layer w0.254: C22.2@71.348,32.635 71.602,32.889 71.602,32.923 72.523,33.844 72.523,33.846 ; U21.28@74.525,34.875 U21.27@75.025,34.875 U21.26@75.525,34.875 U21.25@76.025,34.875 U21.24@76.525,34.875 U21.23@77.025,34.875 U21.22@77.525,34.875 ; U21.39@78.025,36.425 U21.39@78.075,36.475 ; U22.27@84.975,34.848 U22.26@85.475,34.848 U22.25@85.975,34.848 U22.24@86.475,34.848 U22.23@86.975,34.848 U22.22@87.475,34.848 ; U22.39@87.629,36.571 87.658,36.6 v1(87.8,36.6) ; 123.428,48.621 123.675,48.374 U103.33@123.675,47.7
  Bottom Layer w0.4: C120.2@111.825,49.289 C120.2@111.911,49.375 ; C111.2@122.776,51.099 C111.2@122.875,51
  Bottom Layer w0.5: C21.1@69.832,33.571 69.832,33.556 69.956,33.433 70.237,33.433 70.904,32.766 70.915,32.766 70.925,32.756 71.226,32.756 71.3,32.682 71.3,31.65 70.3,30.65 R31.1@70.3,29.2 ; v1(76.9,26.05) 77.527,26.05 77.577,26 U23.4@77.577,25.993 77.577,24.618 ; R25.1@81.786,30.675 81.794,30.667 81.794,29.61 v1(81.803,29.602) ; R37.1@82.575,23.286 82.619,23.331 82.706,23.417 83.367,23.417 83.6,23.65 85.016,23.65 85.364,23.998 85.364,24.608 C36.2@85.495,24.739 ; U22.18@88.825,36.073 88.825,36.048 89.998,34.875 92.45,34.875 C31.2@92.493,34.832 ; C7.2@98.825,47.036 99.239,47.45 v1(99.775,47.45) 100.125,47.1 100.125,46.692 100.35,46.467 C116.2@100.464,46.467 ; C117.1@111.825,47.836 111.825,47.845 111.956,47.976 112.54,47.976 v1(112.789,48.225) ; C111.2@123.087,50.85 R105.1@126.6,50.85
  Bottom Layer w0.6: v1(95.025,59.8) 95.025,61.326 CY101.2@95.035,61.336 ; R110.1@97.428,47.066 C7.2@98.784,47.066 ; R108.1@100.2,45.025 100.387,45.212 100.387,46.391 C116.2@100.464,46.467 ; 105.969,48.95 U102.10@109.4,48.95 ; U102.10@109.4,48.959 C120.2@111.559,48.959 ; C117.1@111.825,47.845 111.825,49.225 111.832,49.232 113.193,49.232 R113.1@113.2,49.239 ; C9.2@129.2,25.961 130.039,26.8 132.338,26.8 133.2,25.938 D4.2@133.2,25.75 C4.2@134.758,25.75
  Bottom Layer w0.7: R24.1@68.5,33.538 C21.1@69.8,33.538 ; C40.2@74.556,24.609 C40.2@74.564,24.618 77.577,24.618 81.029,24.618 C38.2@81.15,24.739 ; C39.2@75.948,24.624 R36.1@75.949,25.988 ; C23.1@80.425,32.039 C24.2@81.803,32.039 ; R25.1@81.786,30.675 81.787,30.676 C24.2@81.789,32.025 C24.2@81.789,32.025 ; R35.1@82.564,24.725 82.557,24.732 81.157,24.732 C38.2@81.15,24.739 ; R37.1@82.575,23.286 82.567,23.294 81.167,23.294 C41.2@81.15,23.311 C38.2@81.15,24.739
  Bottom Layer w0.8: C112.2@134.436,51.268 134.436,49.389 T1.4@134.525,49.3
  Bottom Layer w1: C25.2@38.775,22.35 38.877,22.452 46.388,22.452 50,26.064 50,34.7 57.625,42.325 BD2.4@57.625,42.725 ; pad.13@62.525,43.675 pad.13@62.525,44.375 ; C27.2@63.387,23.113 C27.2@63.45,23.05 ; v1(133.125,54.165) 134.149,54.165 134.284,54.03 C112A.2@134.284,54 C112.2@134.284,51.55
  other v1: 120.8,23.6 121.6,23.6 122.4,23.6 123.2,23.6 124,23.6 119.2,24.4 120,24.4 120.8,24.4 121.6,24.4 122.4,24.4 123.2,24.4 124,24.4 124.8,24.4 125.6,24.4 119.2,25.2 120,25.2 120.8,25.2 121.6,25.2 122.4,25.2 123.2,25.2 124,25.2 124.8,25.2 125.6,25.2 119.2,26 122.4,26 125.6,26 119.2,26.8 122.4,26.8 125.6,26.8 76.8,29.2 77.6,29.2 78.4,29.2 79.2,29.2 85.2,29.2 86,29.2 86.8,29.2 87.6,29.2 88.4,29.2 89.2,29.2 90,29.2 90.8,29.2 91.6,29.2 92.4,29.2 75.2,30 76,30 76.8,30 77.6,30 78.4,30 79.2,30 85.2,30 86,30 86.8,30 87.6,30 88.4,30 89.2,30 90,30 90.8,30 91.6,30 92.4,30 75.2,30.8 76,30.8 76.8,30.8 77.6,30.8 78.4,30.8 85.2,30.8 86,30.8 86.8,30.8 87.6,30.8 88.4,30.8 89.2,30.8 90,30.8 90.8,30.8 91.6,30.8 92.4,30.8 74.4,31.6 75.2,31.6 76,31.6 76.8,31.6 77.6,31.6 78.4,31.6 85.2,31.6 86,31.6 86.8,31.6 87.6,31.6 88.4,31.6 89.2,31.6 90,31.6 90.8,31.6 91.6,31.6 92.4,31.6 71.3,31.7 74.4,32.4 75.2,32.4 76,32.4 76.8,32.4 77.6,32.4 78.4,32.4 85.2,32.4 86,32.4 86.8,32.4 87.6,32.4 88.4,32.4 89.2,32.4 90,32.4 90.8,32.4 91.6,32.4 92.4,32.4 74.4,33.2 75.2,33.2 76,33.2 76.8,33.2 77.6,33.2 78.4,33.2 85.2,33.2 86,33.2 86.8,33.2 87.6,33.2 88.4,33.2 89.2,33.2 90,33.2 90.8,33.2 91.6,33.2 92.4,33.2 74.4,34 75.2,34 76,34 76.8,34 77.6,34 78.4,34 84.4,34 85.2,34 86,34 86.8,34 87.6,34 88.4,34 89.2,34 90,34 90.8,34 91.6,34 90,34.8 90.8,34.8 90,35.6 72.2,35.8 73,35.8 73.8,35.8 74.6,35.8 75.4,35.8 76.2,35.8 77,35.8 85.4,35.8 86.2,35.8 87,35.8 87.8,35.8 72.2,36.6 73,36.6 75.4,36.6 76.2,36.6 77.8,36.6 82.2,36.6 83,36.6 85.4,36.6 86.2,36.6 87,36.6 72.2,37.4 73,37.4 73.8,37.4 74.6,37.4 75.4,37.4 76.2,37.4 77,37.4 77.8,37.4 82.2,37.4 83,37.4 83.8,37.4 84.6,37.4 85.4,37.4 86.2,37.4 87,37.4 87.8,37.4 122.95,45.3 117.675,45.325 118.475,45.325 120.025,45.325 120.875,45.325 121.625,45.325 122.3,45.325 123.625,45.325 119.225,45.35 118.45,46 117.675,46.025 120.025,46.025 122.95,46.075 122.3,46.1 123.625,46.1 119.225,46.125 117.625,46.85 118.425,46.85 119.2,46.85 119.975,46.85 120.825,46.85 123.6,46.825 123.88,52.081
RTN: C3.1 C6.2 C10.2 C104.1 C105.1 C106.2 C107.2 C115.2 C124.2 C127.1 CY1.2 CY2.2 CY101.1 pad.2@115.675,84.95 Q101.1 Q101.2 Q101.3 Q102.1 Q102.2 Q102.3 R102.1 R104.1 R107.1 R122.1 R127.1 R128.2 R129.2 U1.4 U2.2 U105.2 U105.5 | length 125.7
  Top Layer w0.3: v1(111.712,90.559) 112.295,91.142 131.383,91.142 v1@132.475,90.05
  Bottom Layer w0.3: v1(99.536,80.625) 99.556,80.606 99.556,79.581 R104.1@99.575,79.561 ; C10.2@105.622,79.05 105.475,78.902 105.475,78.219 105.402,78.147 105.402,77.42 U1.4@105.359,77.42 106.188,77.42 106.364,77.596 106.364,78.034 106.365,78.035 ; U2.2@106.575,80.875 106.775,80.875 106.925,81.025 106.925,81.211 107.468,81.754 109.447,81.754 111.125,83.432 111.125,88.175 111.125,89.972 v1(111.712,90.559) ; C105.1@109.875,88.1 111.05,88.1 ; 116.9,71.847 Q102.1@116.086,71.847 Q102.2@114.816,71.847 Q102.3@113.546,71.847 113.505,71.888 113.505,72.551 113.685,72.732 116.652,72.732 117.222,73.301 117.222,73.922 117.647,74.348 119.506,74.348 120.271,75.113 120.271,76.97 121.593,78.292 U105.5@121.593,79.655 ; 116.9,71.85 116.903,71.847 ; v1@116.963,69.625 116.963,71.787 116.903,71.847 ; C107.2@118.525,72.95 118.525,72.491 117.881,71.847 116.903,71.847 ; U105.5@121.593,79.814 121.593,80.013 U105.5@121.73,80.15 ; U105.5@121.73,79.655 U105.5@121.73,79.814 ; C106.2@125.85,79.4 126.45,80 126.83,80 127.9,81.07 Q101.3@128.075,81.07 Q101.2@128.075,79.8 128.075,78.635 127.97,78.53 127.9,78.53 127.795,78.425 127.795,78.261 ; R122.1@131.218,89.943 R122.1@131.218,90.025 ; R102.1@131.222,87.01 R102.1@131.718,86.514 ; R122.1@131.289,89.299 131.289,89.525 131.789,90.025 v1(132.55,90.025)
  Bottom Layer w0.35: U105.5@121.73,79.655 121.86,79.525 122.019,79.525 124.027,77.517 127.052,77.517 127.795,78.259 ; U105.5@121.73,79.814 U105.5@121.73,80.15
  Bottom Layer w0.5: 129.688,86.738 129.688,87.22 v1@129.793,87.325 ; 129.688,90.462 129.688,89.801 129.889,89.6 v1(130,89.6) v1(130,88.8) 129.793,88.593 129.793,87.503 ; v1(132.124,71.888) R128.2@132.124,73.301
  Bottom Layer w0.6: pad.2@115.675,84.95 115.675,84.7 114.806,83.831 114.806,83.306 C6.2@114.725,83.225 114.726,83.224 C115.2@116.3,83.222 C115.2@116.3,83.222 117.033,83.955 118.839,83.955 ; R107.1@119.213,88.562 119.213,86.068 119.185,86.04 119.185,84.302 118.839,83.955 ; U105.5@121.73,80.15 121.73,81.75 119.525,83.955 118.839,83.955
  Bottom Layer w1: CY101.1@95.035,71.536 94.575,71.536 93.975,72.136 CY2.2@93.975,86.2 94.131,86.356 C104.1@99.3,86.356 ; 129.707,87.589 129.793,87.503 ; v1@129.793,87.325 130.057,87.589 131.279,87.589 ; R102.1@130.666,87.01 R122.1@130.666,89.714
  other v1: 115.2,69.6 116,69.6 116.8,69.6 117.6,69.6 114.4,70.4 115.2,70.4 116,70.4 116.8,70.4 117.6,70.4 113.6,71.2 114.4,71.2 115.2,71.2 116,71.2 116.8,71.2 117.6,71.2 127.2,79.2 127.2,80 106.602,80.15 124,80.8 124.8,80.8 125.6,80.8 126.4,80.8 127.2,80.8 124,81.6 124.8,81.6 125.6,81.6 124,82.4 124.8,82.4 124,83.2 129.2,86.4 130,86.4 129.2,87.2 130,87.2 129.2,88 130,88 129.2,88.8 129.2,89.6 129.2,90.4 130,90.4
SR_AUX: pad.2@115.7,87.025 R8.1 | length 2.1
  Bottom Layer w0.4: R8.1@113.65,86.947 R8.1@113.689,86.986
  Bottom Layer w0.7: R8.1@113.662,86.96 115.635,86.96 pad.2@115.7,87.025
SR_VDD: C6.1 C115.1 D5.1 U105.7 | length 7.2
  Bottom Layer w0.4: D5.1@112.975,81.825 D5.1@112.986,81.814 ; C115.1@116.3,81.803 118.032,81.803 119.19,80.645 U105.7@119.19,80.15
  Bottom Layer w0.6: D5.1@112.975,81.825 112.978,81.822 C6.1@114.706,81.822 ; C6.1@114.725,81.803 C115.1@116.3,81.803
SW: C101.2 C102.2 C121.1 L3.4 R101.1 U101.17 U101.18 U101.19 U101.21 U101.22 U101.23 U101.24 U101.25 U101.26 U101.27 U101.28 U101.29 U101.32 U101.33 U101.39 U102.16 U103.2 U103.3 U103.4 U103.5 U103.6 U103.7 U103.8 U103.9 U103.10 U103.11 U103.12 U103.13 U103.14 | length 33.2
  Bottom Layer w0.25: 117.7,43.175 119.7,43.175 123.7,43.175 ; U101.39@118.65,35.075 120.225,35.075 121.15,36 U101.32@121.15,36.675 121.15,37.25 121.3,37.4 121.7,37.4 ; U101.33@121.65,36.675 121.65,37.35 121.7,37.4 ; C102.2@122.325,37.875 122.325,37.625 122.1,37.4 121.7,37.4
  Bottom Layer w0.3: C121.1@111.876,41.531 113.256,40.15 117.604,40.15 118.612,39.143 121.423,39.143 122.094,38.472 122.094,38.431 C102.2@122.325,38.2
  Bottom Layer w0.5: C121.1@111.639,41.389 C121.1@111.725,41.475 ; 119.7,43.175 119.708,43.168 119.708,40.632 L3.4@119.715,40.625
  Bottom Layer w0.6: U102.16@109.4,41.339 111.589,41.339 C121.1@111.639,41.389 ; C102.2@122.356,38.169 123.181,38.169 C101.2@124.203,37.148 ; C101.2@124.094,37.117 125.45,37.117 125.625,36.942 R101.1@125.625,36.925
  Bottom Layer w0.7: C102.2@122.341,38.216 122.341,38.184 C102.2@122.356,38.169
  other v1: 118.075,34.3 118.95,34.3 119.7,34.3 115.65,34.325 116.525,34.325 117.325,34.325 120.425,34.325 116.5,35 115.65,35.025 119.675,35.8 117.3,35.825 118.025,35.825 118.9,35.825 120.4,35.825 115.6,35.85 116.475,35.85
  other v2: 118.03,35.875
TSET: R7.1 R119.1 R121.2 U102.7 | length 34.3
  Top Layer w0.5: v1(102.933,48.954) 104.064,50.086 104.064,52.089 v1(106.2,54.225)
  Layer 2 w0.5: v1(96.7,28.405) 97.547,29.252 97.547,42.147 102.933,47.533 v1(102.933,48.954)
  Bottom Layer w0.254: R119.1@105.511,53.3 R119.1@105.625,53.3 ; R121.2@106.937,53.3 R121.2@106.939,53.299
  Bottom Layer w0.5: R7.1@96.7,27.361 v1(96.7,28.405) ; v1(106.2,54.225) 106.2,53.381 106.281,53.3
  Bottom Layer w0.6: v1(102.933,48.954) 102.937,48.95 U102.7@104,48.95 ; R119.1@105.511,53.3 R119.1@105.511,53.3 ; R119.1@105.625,53.3 106.281,53.3 R121.2@106.937,53.3 ; R121.2@106.939,53.299 R121.2@106.94,53.297
VAUX: C112.1 C112A.1 D101.1 D103.1 Q1.3 R4.2 | length 75.4
  Bottom Layer w0.254: C112.1@135.742,51.994 C112.1@136.25,51.486
  Bottom Layer w0.5: R4.2@129.2,21.689 R4.2@129.218,21.707 ; Q1.3@131.932,21.707 Q1.3@131.95,21.725
  Bottom Layer w0.6: D103.1@110.075,58.025 133.14,58.025 135.986,55.178 135.986,54.33 C112A.1@136.316,54 ; R4.2@129.218,21.707 Q1.3@131.932,21.707 ; Q1.3@131.95,21.725 131.95,21.525 132.15,21.525 132.867,20.808 136.548,20.808 139.175,23.435 139.175,44.73 136.44,47.465 136.44,51.296 C112.1@136.25,51.486 ; C112A.1@136.316,54.165 136.651,54.5 136.892,54.5 D101.1@138.431,56.04
  Bottom Layer w1: C112.1@136.25,51.486 C112A.1@136.25,54
VCCP: C4.1 C110.1 C117.2 C128.2 D1.1 D102.2 Q2.3 R5.1 R6.2 U102.12 U103.30 U103.36 | length 117.8
  Layer 1 w0.6: v1(124.425,49.925) 124.425,51.453 126.3,53.328 134.525,53.328 136.325,51.528 136.325,47.814 139.057,45.082 139.057,26.072 C4.1@137.026,24.041
  Layer 2 w0.4: v1@91.054,27.2 95.272,27.2
  Layer 2 w0.6: v1(95.272,29.75) 95.272,27.2 95.272,23.51 97.861,20.921 133.817,20.921 C4.1@136.937,24.041
  Bottom Layer w0.25: v1(121.85,49.225) 121.85,49.157 122.175,48.832 U103.30@122.175,47.9 ; U103.36@124.55,46.475 125.175,46.475 125.357,46.657 125.357,49.182 C110.1@125.175,49.364
  Bottom Layer w0.4: v1@91.043,27.207 v1(91.05,27.2) Q2.3@91.95,27.2 ; R6.2@95.272,27.31 R6.2@95.317,27.355
  Bottom Layer w0.5: v1(95.272,29.75) 95.272,27.401 R6.2@95.317,27.355 ; C128.2@110.061,59.7 110.939,59.7 v1(111.314,59.325) ; v1(124.425,49.925) 124.425,49.924 124.854,49.495 125.044,49.495 C110.1@125.175,49.364
  Bottom Layer w0.508: D1.1@134.7,21.825 134.746,21.871 134.808,21.871 C4.1@136.978,24.041
  Bottom Layer w0.6: U102.12@109.4,46.419 C117.2@111.455,46.419 ; C128.2@110.061,59.7 C128.2@110.075,59.686 ; C117.2@111.825,46.414 v1(112.868,46.414) 113.911,46.414 D102.2@114.373,46.875
VDH: C125.2 Q101.5 Q101.6 Q101.7 Q101.8 Q101.9@131.975,80.435 R130.1 T1.9 | length 13.5
  Bottom Layer w0.305: R130.1@124.511,85.4 124.68,85.231 125.14,85.231 127.065,83.306 129.234,83.306 131.975,80.565 Q101.9@131.975,80.435 ; T1.9@132.4,76.075 132.761,76.075 133.611,75.225 C125.2@135.975,75.225
VDL: C126.2 Q102.5 Q102.6 Q102.7 Q102.8 Q102.9@114.181,75.747 R131.1 T1.5 | length 23.8
  Layer 2 w0.5: T1.5@118.4,76.075 118.242,75.917 118.242,72.412 119.78,70.875 v1(124.097,70.875)
  Bottom Layer w0.35: Q102.5@112.208,77.396 112.208,77.73 112.196,77.742 111.955,77.742 111.58,78.117 111.58,78.982 112.473,79.875 116.2,79.875 117.603,78.472 R131.1@118.16,78.472 ; Q102.5@112.276,77.522 114.051,75.747 Q102.9@114.181,75.747 Q102.9@113.841,75.747
  Bottom Layer w0.5: C126.2@124.097,69.775 v1(124.097,70.875)
VFB: C3.2 C8.1 C104.2 C105.2 C106.1 C107.1 C113.1 C124.1 R3.2 R9.2 R117.2 R126.1 T1.6 T1.8 TP101.1 U1.8 | length 53.6
  Layer 2 w0.4: C104.2@102.8,86.356 102.8,85.275 97.6,80.075 97.6,71.862 98.587,70.875 105.068,70.875 105.929,71.736 v1(105.929,72.607)
  Bottom Layer w0.25: C124.1@108.559,73.877 C124.1@108.561,73.875
  Bottom Layer w0.3: C124.1@108.559,73.877 U1.8@108.559,75.92
  Bottom Layer w0.5: R126.1@105.636,73.85 105.759,73.727 105.759,72.777 v1(105.929,72.607) ; v1@105.944,72.592 107.768,72.592 108.43,73.254 108.43,73.744 C124.1@108.561,73.875
  Bottom Layer w0.7: R117.2@98.125,76.856 98.125,80.705 99.831,82.411 R3.2@101.05,82.411 C8.1@102.55,82.411 102.581,82.442 102.581,84.6 ; R117.2@98.14,76.726 C113.1@99.56,76.726 ; C104.2@102.8,86.356 102.581,86.137 102.581,84.6 ; R9.2@105.18,84.499 105.149,84.53 102.651,84.53 102.581,84.6 ; C106.1@125.8,76.3 125.912,76.188 128.637,76.188 T1.8@128.75,76.075
VGH: Q101.4 U105.1 | length 12.9
  Top Layer w0.5: v1(117.225,85.55) 123.406,85.55 v1(126.506,82.45)
  Bottom Layer w0.5: v1(117.225,85.55) U105.1@117.92,85.55 ; v1(126.506,82.45) 126.616,82.34 Q101.4@128.075,82.34
VGL: Q102.4 U105.8 | length 16
  Bottom Layer w0.4: Q102.4@112.331,71.953 112.331,71.967 112.221,72.077 112.033,72.077 110.849,73.261 110.849,79.152 112.301,80.604 117.815,80.604 117.92,80.499 U105.8@117.92,80.15
pads on no net: Q101.9@130.715,78.965 Q101.9@130.715,80.435 Q101.9@130.715,81.905 Q101.9@132.395,78.965 Q101.9@132.395,80.435 Q101.9@132.395,81.905 Q102.9@112.711,74.487 Q102.9@112.711,76.167 Q102.9@114.181,74.487 Q102.9@114.181,76.167 Q102.9@115.651,74.487 Q102.9@115.651,76.167 U21.14 U21.16 U21.20 U21.34 U21.35 U21.38 U22.15 U22.16 U22.20 U22.34 U22.35 U22.38 U101.1 U101.15 U101.16 U101.20 U101.34 U101.35 U101.38 U103.1 U103.15 U103.16 U103.20 U103.34 U103.35 U103.38

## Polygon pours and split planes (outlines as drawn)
NetC2_2 on Bottom Layer "BOTTOM_LAYER_NETC2_2_P354" (solid, remove dead copper, pour order 354): 24 vertices, not listed, extent 35.625,41.35 50.025,68.75
NetC2_1 on Bottom Layer "BOTTOM_LAYER_NETC2_1_P353" (solid, remove dead copper, pour order 353): 17 vertices, not listed, extent 35.436,51.4 41.561,68.527
NetC1_1 on Bottom Layer "BOTTOM_LAYER_NETC1_1_P348" (solid, remove dead copper, pour order 348): 19 vertices, not listed, extent 44.325,70.625 50.125,90.525
NetF1_2 on Bottom Layer "BOTTOM_LAYER_NETF1_2_P344" (solid, remove dead copper, pour order 344): 41.8,88.125 41.4,87.725 35.65,87.725 35.4,87.975 35.4,90.075 36,90.675 40.725,90.675 41.8,89.6
NetC1_2 on Bottom Layer "BOTTOM_LAYER_NETC1_2_P343" (solid, remove dead copper, pour order 343): 21 vertices, not listed, extent 35.401,70.629 42.175,83.65
NetL3_1 on Bottom Layer "BOTTOM_LAYER_NETL3_1_P337" (solid, remove dead copper, pour order 337): 126.45,40.45 126.95,39.95 128.975,39.95 129.275,40.25 129.275,44.849 128.724,45.4 127.383,45.4 126.45,44.467
PGND on Bottom Layer "BOTTOM_LAYER_PGND_P333" (solid, remove dead copper, pour order 333): 118.773,27.3 127.577,27.3 128.053,26.823 128.053,21.695 127.383,21.025 119.395,21.025 118.375,22.045 118.375,26.902
VFB on Bottom Layer "BOTTOM_LAYER_VFB_P323" (solid, remove dead copper, pour order 323): 101.825,86.175 102.25,85.75 106.975,85.75 107.675,85.05 107.675,84 108.025,83.65 110.15,83.65 110.7,84.2 110.7,86.6 110.175,87.125 107.85,87.125 107.3,87.675 102.35,87.675 101.825,87.15
RTN on Bottom Layer "BOTTOM_LAYER_RTN_P322" (solid, remove dead copper, pour order 322): 110.225,87.375 110.675,87.825 110.675,90.05 109.8,90.925 99.1,90.925 98.275,90.1 98.275,85.3 98.925,84.65 100.55,84.65 101.25,85.35 101.25,87.125 102.175,88.05 107.9,88.05 108.575,87.375
VFB on Bottom Layer "BOTTOM_LAYER_VFB_P321" (solid, remove dead copper, pour order 321): 128.8,85.2 128.15,85.85 127.175,85.85 126.8,85.475 126.8,84.4 127.425,83.775 130.225,83.775 130.6,83.4 136.2,83.4 137.2,82.4 138.8,82.4 139.175,82.775 139.175,84.9 138.875,85.2
OCP on Bottom Layer "BOTTOM_LAYER_OCP_P320" (solid, remove dead copper, pour order 320): 133.525,85.725 139.025,85.725 139.325,86.025 139.325,90.55 138.8,91.075 134.051,91.075 133.689,90.713 133.689,89.595 133.525,89.431
RTN on Bottom Layer "BOTTOM_LAYER_RTN_P319" (solid, remove dead copper, pour order 319): 131.975,90.2 131.45,90.725 122.56,90.725 121.64,89.805 121.64,87.38 122.506,86.514 128.211,86.514 129,85.725 131.975,85.725
VDH on Bottom Layer "BOTTOM_LAYER_VDH_P318" (solid, remove dead copper, pour order 318): 129.793,82.747 129.793,78.157 131.218,76.732 131.218,75.378 131.846,74.75 136.825,74.75 137.65,75.575 137.65,81.075 135.963,82.762 129.778,82.762
RTN on Bottom Layer "BOTTOM_LAYER_RTN_P317" (solid, remove dead copper, pour order 317): 116.8,72.275 117.8,73.275 117.8,73.7 119.3,73.7 119.3,69 119.125,68.825 115.025,68.825 113.3,70.55 113.3,72.1 113.475,72.275
VDL on Bottom Layer "BOTTOM_LAYER_VDL_P316" (solid, remove dead copper, pour order 316): 18 vertices, not listed, extent 111.475,73.575 119.5,79.425
VFB on Bottom Layer "BOTTOM_LAYER_VFB_P314" (solid, remove dead copper, pour order 314): 129.025,77.2 127.875,77.2 127.375,76.7 123.1,76.7 122.625,77.175 121.425,77.175 120.875,76.625 120.875,71.75 129.275,71.75 130.475,72.95 130.475,76.55 129.825,77.2
RTN on Bottom Layer "BOTTOM_LAYER_RTN_P313" (solid, remove dead copper, pour order 313): 126.5,81.325 125.85,81.975 125.85,83.55 125.525,83.875 123.8,83.875 123.225,83.3 123.225,79.4 124.325,78.3 128.475,78.3 128.5,78.325 128.5,81.2 128.375,81.325
RTN on Bottom Layer "BOTTOM_LAYER_RTN_P312" (solid, remove dead copper, pour order 312): 18 vertices, not listed, extent 116.225,81.25 122.9,87
NetC103_2 on Bottom Layer "BOTTOM_LAYER_NETC103_2_P082" (solid, remove dead copper, pour order 207): 129.25,49.225 129.25,46.475 130.6,45.125 130.6,41.175 133.125,38.65 136,38.65 136.7,39.35 136.7,43.52 134.025,46.195 130.995,49.225
390V_BUS on Bottom Layer "BOTTOM_LAYER_390V_BUS_P186" (solid, remove dead copper, pour order 186): 35 vertices, not listed, extent 90.4,21.025 136.96,42.641
PGND on Bottom Layer "BOTTOM_LAYER_PGND_P310" (solid, remove dead copper, pour order 310): 106.3,37.1 108.094,37.1 108.954,36.24 108.954,34.639 112.675,30.917 112.675,29.65 111.875,28.85 110.628,28.85 105.75,33.728 105.75,36.55
390V_BUS on Bottom Layer "BOTTOM_LAYER_390V_BUS_P270" (solid, remove dead copper, pour order 270): 69.215,59.484 69.215,51.475 71.925,51.475 71.925,59.484
BD+ on Bottom Layer "BOTTOM_LAYER_BD+_P264" (solid, remove dead copper, pour order 264): 19 vertices, not listed, extent 52.675,51.475 66.925,90.525
NetBD2_2 on Bottom Layer "BOTTOM_LAYER_NETBD2_2_P261" (solid, remove dead copper, pour order 261): 17 vertices, not listed, extent 50.6,41.375 59,54.075
BD+ on Bottom Layer "BOTTOM_LAYER_BD+_P252" (solid, remove dead copper, pour order 252): 64.1,90.525 67.925,90.525 70,88.45 70,63.4 66.55,59.95 63.999,59.95
NetBD1_2 on Bottom Layer "BOTTOM_LAYER_NETBD1_2_P239" (solid, remove dead copper, pour order 239): 58.425,75 51.425,75 50.525,74.1 50.525,68.575 52.075,67.025 58.1,67.025 59.25,68.175 59.25,74.175
PGND on Bottom Layer "BOTTOM_LAYER_PGND_P233" (solid, remove dead copper, pour order 233): 26 vertices, not listed, extent 36.3,21.05 65.325,48.625
NetBD2_2 on Bottom Layer "BOTTOM_LAYER_NETBD2_2_P229" (solid, remove dead copper, pour order 229): 17 vertices, not listed, extent 50.6,41.375 59,54.075
BD+ on Bottom Layer "BOTTOM_LAYER_BD+_P231" (solid, remove dead copper, pour order 231): 27 vertices, not listed, extent 36.825,28.45 55.9,59.325
NetC28_1 on Bottom Layer "BOTTOM_LAYER_NETC28_1_P161" (solid, remove dead copper, pour order 161): 35 vertices, not listed, extent 64.54,29.775 94.65,47.65
RTN on Bottom Layer "BOTTOM_LAYER_RTN_P224" (solid, remove dead copper, pour order 224): 107.55,81.9 106.1,81.9 105.25,81.05 105.25,77.791 106.025,77.016 106.025,74.9 106.25,74.675 106.478,74.675 106.75,74.403 106.75,73.6 107.525,73.6 107.525,74.666 107.95,75.091 107.95,80.096 107.55,80.496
